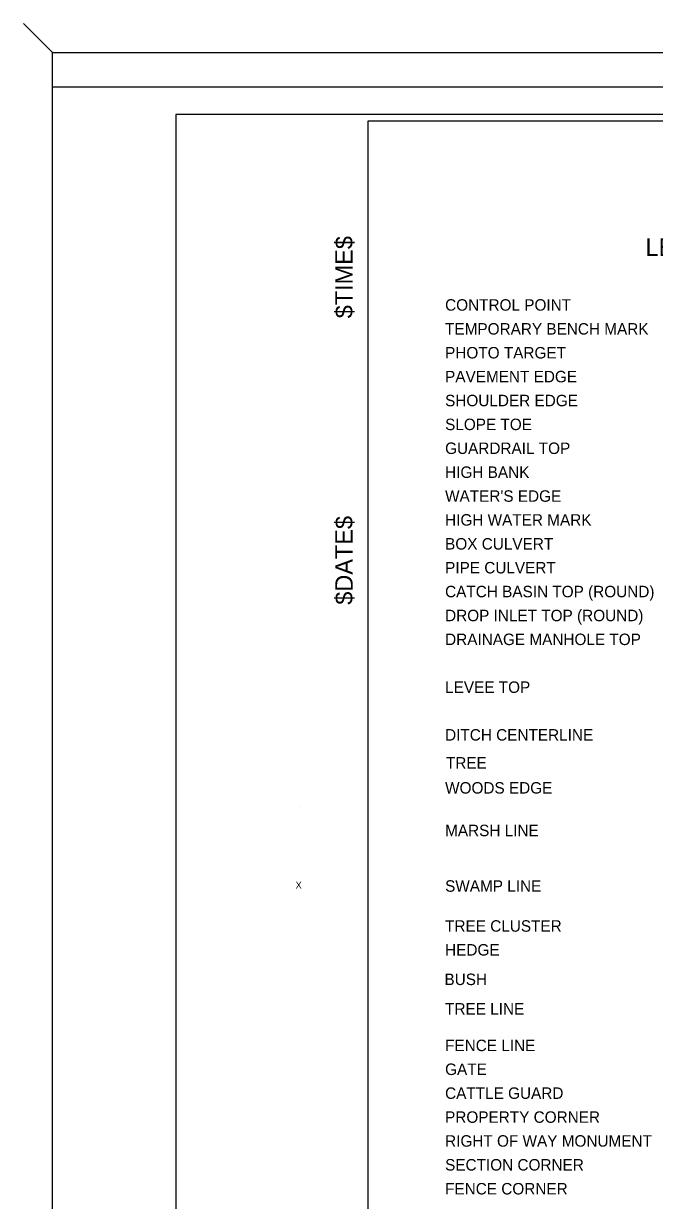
# Model space of a CAD drawing. Extents: x -1.93 to 2.83, y -1.79 to 1.85.
# Drawn here: x -0.018 to 0.366, y 1.136 to 1.851 of the extents above; entities that cross this region are included whole.
import ezdxf

# ---------------------------------------------------------------- set-up
doc = ezdxf.new("R2010")
doc.units = 0
for name, color, linetype in [('Construction Class', 7, 'Continuous'), ('Legend', 7, 'Continuous'), ('Plot Border', 7, 'Continuous'), ('Plot Border 2', 7, 'Continuous'), ('Sheet Border', 7, 'Continuous')]:
    doc.layers.add(name, color=color, linetype=linetype)

msp = doc.modelspace()

# ---------------------------------------------------------------- linework, layer by layer
at = {"layer": 'Construction Class'}
msp.add_line((0.15, 1.375), (0.15, 1.375), dxfattribs=at)
at = {"layer": 'Plot Border'}
msp.add_line((0, 1.83333), (-0.01768, 1.85101), dxfattribs=at)
for points in [[(0, 1.83333), (2.83333, 1.83333), (2.83333, 0), (0, 0)], [(2.825, 1.79583), (0.075, 1.79583), (0.075, 0.0375), (2.825, 0.0375)]]:
    msp.add_lwpolyline(points, close=True, dxfattribs=at)
at = {"layer": 'Plot Border 2'}
msp.add_lwpolyline([(0, 1.8125), (2.83333, 1.8125), (2.83333, 0.02083), (0, 0.02083)], close=True, dxfattribs=at)
at = {"layer": 'Sheet Border'}
for p, q in [((2.81667, 1.79167), (0.19167, 1.79167)), ((0.19167, 1.79167), (0.19167, 0.04167))]:
    msp.add_line(p, q, dxfattribs=at)

# ---------------------------------------------------------------- texts
at = {"layer": 'Legend'}
for s, height, p in [('CONTROL POINT', 0.0069667, (0.23871, 1.67653)), ('TEMPORARY BENCH MARK', 0.0069667, (0.23871, 1.66199)), ('PHOTO TARGET', 0.0069667, (0.23871, 1.64749)), ('PAVEMENT EDGE', 0.0069667, (0.23871, 1.63299)), ('SHOULDER EDGE', 0.0069667, (0.23871, 1.61845)), ('SLOPE TOE', 0.006967, (0.23871, 1.60395)), ('GUARDRAIL TOP', 0.0069667, (0.23871, 1.58945)), ('HIGH BANK', 0.006967, (0.23871, 1.57491)), ("WATER'S EDGE", 0.0069667, (0.23871, 1.56041)), ('HIGH WATER MARK', 0.0069667, (0.23871, 1.54591)), ('BOX CULVERT', 0.0069667, (0.23871, 1.53137)), ('PIPE CULVERT', 0.0069667, (0.23871, 1.51687)), ('CATCH BASIN TOP (ROUND)', 0.0069667, (0.23871, 1.50237)), ('DROP INLET TOP (ROUND)', 0.0069667, (0.23871, 1.48783)), ('DRAINAGE MANHOLE TOP', 0.0069667, (0.23871, 1.47333)), ('LEVEE TOP', 0.006967, (0.23871, 1.44428)), ('DITCH CENTERLINE', 0.0069667, (0.23871, 1.41528)), ('TREE', 0.006967, (0.23921, 1.39828)), ('WOODS EDGE', 0.006967, (0.23871, 1.38308)), ('MARSH LINE', 0.006967, (0.23871, 1.3572)), ('SWAMP LINE', 0.006967, (0.23871, 1.32345)), ('TREE CLUSTER', 0.0069667, (0.23871, 1.29916)), ('HEDGE', 0.006967, (0.23871, 1.28466)), ('BUSH', 0.006967, (0.23833, 1.26674)), ('TREE LINE', 0.006967, (0.23871, 1.24883)), ('FENCE LINE', 0.006967, (0.23871, 1.22658)), ('GATE', 0.006967, (0.23871, 1.21208)), ('CATTLE GUARD', 0.0069667, (0.23871, 1.19758)), ('PROPERTY CORNER', 0.0069667, (0.23871, 1.18303)), ('RIGHT OF WAY MONUMENT', 0.0069667, (0.23871, 1.16853)), ('SECTION CORNER', 0.0069667, (0.23871, 1.15403)), ('FENCE CORNER', 0.0069667, (0.23871, 1.13949))]:
    msp.add_text(s, height=height, dxfattribs=at).set_placement(p)
at = {"layer": 'Plot Border'}
for s, p in [('$TIME$', (0.18255, 1.6719)), ('$DATE$', (0.18255, 1.49785))]:
    msp.add_text(s, height=0.010667, rotation=90, dxfattribs=at).set_placement(p)
at = {"layer": 'Sheet Border'}
for s, height, p in [('LEGEND - EXISTING TOPOGRAPHY', 0.01067, (0.3606, 1.70972)), ('X', 0.00417, (0.14778, 1.32537))]:
    msp.add_text(s, height=height, dxfattribs=at).set_placement(p)

doc.saveas('drawing.dxf')
